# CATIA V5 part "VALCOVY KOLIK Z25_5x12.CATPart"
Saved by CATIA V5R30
Part number: VALCOVY KOLIK Z25/5x12
Bounding box of the stored display mesh (mm): x -11.992 to 0, y -2.5 to 2.5, z -2.5 to 2.5
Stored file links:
  C:\Users\ondra\Desktop\PŘÍLOHA P III\CATIA\VALCOVY KOLIK Z25_5x12.CATPart
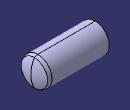
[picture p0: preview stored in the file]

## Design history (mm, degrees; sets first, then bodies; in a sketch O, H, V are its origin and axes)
Set1
  DatumSurface1 to DatumSurface8 "Z25/5x12"
  Plane1: type Offset, RefPlane yz-plane, Offset 6, reversed
  Join1: Elements (DatumSurface1; DatumSurface2; DatumSurface3; DatumSurface4; DatumSurface5; DatumSurface6; DatumSurface7; DatumSurface8)
Body1 (main body)
  CloseSurface1: CloseElement Join1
